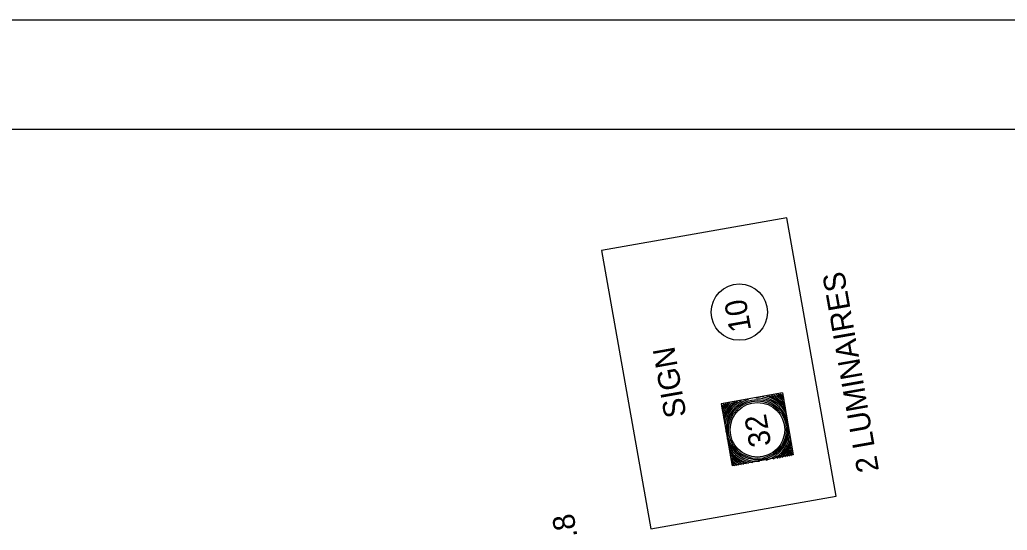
# Model space of a CAD drawing. Extents: x 36 to 2622, y -5330 to 219.
# Drawn here: x 2300.3 to 2435.5, y -4211.8 to -4141.8 of the extents above; entities that cross this region are included whole.
import ezdxf

# ---------------------------------------------------------------- set-up
doc = ezdxf.new("R2010")
doc.units = 0
for name, color, linetype in [('1', 7, 'Continuous'), ('2', 7, 'Continuous'), ('PLT-BNDY', 7, 'Continuous')]:
    doc.layers.add(name, color=color, linetype=linetype)

msp = doc.modelspace()

# ---------------------------------------------------------------- linework, layer by layer
at = {"layer": '1'}
msp.add_line((1757.86, -4156.83), (2543.86, -4156.83), dxfattribs=at)
at = {"layer": '2'}
msp.add_lwpolyline([(2412.11, -4207.08), (2405.36, -4168.95), (2379.98, -4173.45), (2386.73, -4211.58)], close=True, dxfattribs=at)
for points in [[(2404.73, -4192.95), (2396.36, -4194.45)], [(2404.73, -4192.95), (2406.23, -4201.45)], [(2396.36, -4194.45), (2397.86, -4202.95)], [(2406.23, -4201.45), (2397.86, -4202.95)]]:
    msp.add_lwpolyline(points, dxfattribs=at)
for centre, radius in [((2398.84, -4181.88), 3.86), ((2401.32, -4198), 4.13), ((2401.32, -4198), 3.95), ((2401.32, -4198), 3.74)]:
    msp.add_circle(centre, radius, dxfattribs=at)
for radius, start, end in [(4.53, 28.7747, 81.2253), (4.73, 34.969, 75.031), (4.89, 38.6036, 71.3964), (5.06, 42.1022, 67.8978), (5.26, 45.3377, 64.6623), (5.45, 48.0414, 61.9586), (5.62, 50.231, 59.769), (5.8, 52.2801, 57.7199), (5.8, 142.2801, 147.7872), (5.62, 140.231, 149.8414), (5.45, 138.0414, 152.0368), (5.26, 135.3377, 154.7486), (5.06, 132.1022, 157.9954), (4.89, 128.6036, 161.5088), (4.73, 124.969, 165.1626), (4.53, 118.7747, 171.406), (4.32, 106.9038, 183.621), (4.32, 16.9038, 93.0962), (4.32, 286.379, 3.0962), (4.53, 298.594, 351.2253), (4.32, 196.379, 273.621), (4.53, 208.594, 261.406), (4.73, 304.8374, 345.031), (4.89, 308.4912, 341.3964), (5.06, 312.0046, 337.8978), (5.26, 315.2513, 334.6623), (4.73, 214.8374, 255.1626), (4.89, 218.4912, 251.5088), (5.06, 222.0046, 247.9954), (5.26, 225.2513, 244.7486), (5.45, 317.9632, 331.9586), (5.62, 320.1586, 329.769), (5.8, 322.2128, 327.7199), (5.45, 227.9632, 242.0368), (5.62, 230.1586, 239.8414), (5.8, 232.2128, 237.7872)]:
    msp.add_arc((2401.32, -4198), radius, start, end, dxfattribs=at)
at = {"layer": 'PLT-BNDY'}
msp.add_lwpolyline([(1717.86, -4141.83), (2558.86, -4141.83), (2558.86, -4735.83), (1717.86, -4735.83)], close=True, dxfattribs=at)

# ---------------------------------------------------------------- texts
at = {"layer": '2'}
for s, height, p in [('2 LUMINAIRES', 2.9955, (2417.98, -4203.58)), ('10', 2.996, (2400.48, -4184.33)), ('SIGN', 2.996, (2391.61, -4196.08)), ('32', 2.996, (2403.23, -4200.08)), ('SIGN STRUCTURE NO.8', 2.9955, (2384.11, -4254.7))]:
    msp.add_text(s, height=height, rotation=100, dxfattribs=at).set_placement(p)

doc.saveas('drawing.dxf')
